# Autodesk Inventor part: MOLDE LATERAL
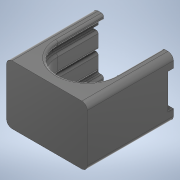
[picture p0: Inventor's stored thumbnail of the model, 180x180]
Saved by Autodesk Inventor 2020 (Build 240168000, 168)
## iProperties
Created: 2022-09
Part Number: MOLDE LATERAL
Material: PVC, no plastificado
Document SubType Name: Modeling
Designer: SEBAS
Density: 1.29 g/cm^3
Appearance: Suave - Negro
Author: SEBAS
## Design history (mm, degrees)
sketch "Boceto3"
  geometry: L1 (37, 54)-(37, 0); L2 (37, 0)-(27, 0); L3 (27, 0)-(27, 5); L4 (27, 5)-(32, 5); L5 (32, 5)-(32, 11); L6 (32, 11)-(27, 11); L7 (27, 11)-(27, 26); L8 (27, 26)-(32, 26); L9 (32, 26)-(32, 28); L10 (32, 28)-(27, 28); L11 (27, 28)-(27, 43); L12 (27, 43)-(32, 43); L13 (32, 43)-(32, 49); L14 (32, 49)-(27, 49); L15 (27, 49)-(27, 54); L16 (27, 54)-(37, 54); L17 (0, 0)-(0, 55); L18 (27, 5)-(27, 11); L19 (27, 26)-(27, 28); L20 (27, 49)-(27, 43); L21 (32, 49)-(32, 54); L22 (32, 5)-(32, 0)
  constraints: 44 end point, 10 perpendicular, 8 point on line, 5 collinear, 3 vertical, 2 horizontal alignment, 2 midpoint, 1 horizontal, 1 vertical alignment
  dimensions: "d27" = 32 distance from line of L17.start L5; "d28" = 10 distance of L1.end L2.end; "d29" = 5 distance of L4.end L3.end; "d30" = 5 distance of L14.end L15.end; "d33" = 2 distance of L8.end L9.end; "d34" = 15 distance of L10.end L11.end; "d35" = 6 distance of L4.end L5.end
sketch "Boceto4"
  geometry: L1 (0, -13.5)-(0, 13.5); L2 (37, 37)-(-37, 37); L3 (-37, 37)-(-37, -37); L4 (-37, -37)-(37, -37); L5 (37, -37)-(37, 37); L6 (37, 37)-(-37, -37); L7 (-37, 37)-(37, -37); L8 (-27, 27)-(27, 27); L9 (27, 27)-(27, -27); L10 (27, -27)-(-27, -27); L11 (-27, -27)-(-27, 27); L12 (-27, 27)-(27, -27); L13 (27, 27)-(-27, -27); L14 (37, 0)-(-37, 0); 4 further points
  constraints: 28 end point, 7 midpoint, 4 parallel, 4 perpendicular, 2 horizontal, 1 coincident
  dimensions: "d38" = 37 horizontal distance of L2.end point (0, 0); "d39" = 10 distance between parallel lines of L2 L8
revolve "Revolución2" stored, may be unused: angle "d40" = 180 deg
extrude "Extrusión2" join sketch "Boceto4" stored distance "d41" = 10; taper "d42" = 0 deg
revolve "Revolución3" stored, may be unused: angle "d43" = 90 deg
fillet "Empalme2" dims "d44" = 5
sketch "Boceto5"
  geometry: L1 (5, 5)-(0, 5) reference; L2 (0, 5)-(0, 0) reference; L3 (0, 0)-(5, 0) reference; L4 (5, 0)-(5, -6) reference; L5 (5, -6)-(0, -6) reference; L6 (0, -6)-(0, -21) reference; L7 (0, -21)-(5, -21) reference; L8 (5, -21)-(5, -23) reference; L9 (5, -23)-(0, -23) reference; L10 (0, -23)-(0, -38) reference; L11 (0, -38)-(5, -38) reference; L12 (5, -38)-(5, -44) reference; L13 (5, -44)-(0, -44) reference; L14 (0, -44)-(0, -49) reference; L15 (0, -49)-(5, -49) reference; L16 (10, -44)-(10, 0) reference; L17 (-64, -44)-(-64, 0) reference; L18 (-54, -49)-(-59, -49) reference; L19 (-54, -44)-(-54, -49) reference; L20 (-54, -44)-(-59, -44) reference; L21 (-59, -44)-(-59, -38) reference; L22 (-59, -38)-(-54, -38) reference; L23 (-54, -23)-(-54, -38) reference; L24 (-54, -23)-(-59, -23) reference; L25 (-59, -23)-(-59, -21) reference; L26 (-59, -21)-(-54, -21) reference; L27 (-54, -6)-(-54, -21) reference; L28 (-54, -6)-(-59, -6) reference; L29 (-59, -6)-(-59, 0) reference; L30 (-59, 0)-(-54, 0) reference; L31 (-54, 5)-(-54, 0) reference; L32 (-59, 5)-(-54, 5) reference; L33 (0, -23)-(0, -38) reference; L34 (0, -30.5)-(10, -30.5); L35 (0, -6)-(0, -21) reference; L36 (0, -13.5)-(10, -13.5); L37 (-54, -30.5)-(-64, -30.5); L38 (-54, -6)-(-54, -21) reference; L39 (-54, -13.5)-(-64, -13.5); L40 (-64, -44)-(-64, 0) reference; L41 (7.5, -28)-(2.5, -28); L42 (2.5, -28)-(2.5, -33); L43 (2.5, -33)-(7.5, -33); L44 (7.5, -33)-(7.5, -28); L45 (7.5, -28)-(2.5, -33); L46 (2.5, -28)-(7.5, -33); L47 (-56, -27.5)-(-62, -27.5); L48 (-62, -27.5)-(-62, -33.5); L49 (-62, -33.5)-(-56, -33.5); L50 (-56, -33.5)-(-56, -27.5); L51 (-56, -27.5)-(-62, -33.5); L52 (-62, -27.5)-(-56, -33.5); L53 (-56.5, -11)-(-61.5, -11); L54 (-61.5, -11)-(-61.5, -16); L55 (-61.5, -16)-(-56.5, -16); L56 (-56.5, -16)-(-56.5, -11); L57 (-56.5, -11)-(-61.5, -16); L58 (-61.5, -11)-(-56.5, -16); L59 (8, -10.5)-(2, -10.5); L60 (2, -10.5)-(2, -16.5); L61 (2, -16.5)-(8, -16.5); L62 (8, -16.5)-(8, -10.5); L63 (8, -10.5)-(2, -16.5); L64 (2, -10.5)-(8, -16.5)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; A1 r 5 centre (5, 0) between (10, 0) and (5, 5) reference; A2 r 5 centre (5, -44) between (5, -49) and (10, -44) reference; A3 r 5 centre (-59, 0) between (-59, 5) and (-64, 0) reference; A4 r 5 centre (-59, -44) between (-64, -44) and (-59, -49) reference; 9 further points; 1 other entity
  constraints: 60 end point, 15 midpoint, 9 parallel, 7 point on line, 6 equal length, 6 perpendicular, 4 horizontal, 1 vertical, 2 other
  dimensions: "d45" = 5 distance of L42.end L43.end; "d51" = 6 distance of L48.end L49.end
  node "Contorno proyectado1"
  node "Contorno proyectado2"
sketch "Boceto6"
  geometry: L1 (32, 28)-(-32, 28) reference; L2 (32, 26)-(32, 28) reference; L3 (32, 26)-(-32, 26) reference; L4 (-32, 28)-(-32, 26) reference; L5 (32, 27)-(-32, 27); L6 (-32, 28)-(-32, 26) reference; L7 (12.5, 14.5)-(-12.5, 14.5); L8 (-12.5, 14.5)-(-12.5, 39.5); L9 (-12.5, 39.5)-(12.5, 39.5); L10 (12.5, 39.5)-(12.5, 14.5); L11 (12.5, 14.5)-(-12.5, 39.5); L12 (-12.5, 14.5)-(12.5, 39.5); 2 further points
  constraints: 14 end point, 5 midpoint, 2 parallel, 2 perpendicular, 1 horizontal
  dimensions: "d53" = 25 distance of L8.end L9.end
extrude "Extrusión5" cut sketch "Boceto6" distance "d54" = 33; taper "d55" = 0 deg
fillet "Empalme5" dims "d56" = 2
fillet "Empalme7" dims "d60" = 1
fillet "Empalme8" dims "d61" = 1
extrude "Extrusión7" join sketch "Boceto5" distance "d65" = 42; taper "d66" = 0 deg
sketch "Boceto8"
  geometry: L1 (0, -6)-(0, -21) reference; L2 (0, -21)-(5, -21) reference; L3 (5, -21)-(5, -23) reference; L4 (5, -23)-(0, -23) reference; L5 (0, -23)-(0, -38) reference; L6 (0, -38)-(5, -38) reference; L7 (5, -38)-(5, -44) reference; L8 (5, -44)-(0, -44) reference; L9 (0, -44)-(0, -49) reference; L10 (0, -49)-(5, -49) reference; L11 (10, -44)-(10, 0) reference; L12 (5, 5)-(0, 5) reference; L13 (0, 5)-(0, 0) reference; L14 (0, 0)-(5, 0) reference; L15 (5, 0)-(5, -6) reference; L16 (5, -6)-(0, -6) reference; L17 (-59, 0)-(-54, 0) reference; L18 (-54, 0)-(-54, 5) reference; L19 (-54, 5)-(-59, 5) reference; L20 (-64, 0)-(-64, -44) reference; L21 (-59, -49)-(-54, -49) reference; L22 (-54, -49)-(-54, -44) reference; L23 (-54, -44)-(-59, -44) reference; L24 (-59, -44)-(-59, -38) reference; L25 (-59, -38)-(-54, -38) reference; L26 (-54, -38)-(-54, -23) reference; L27 (-54, -23)-(-59, -23) reference; L28 (-59, -23)-(-59, -21) reference; L29 (-59, -21)-(-54, -21) reference; L30 (-54, -21)-(-54, -6) reference; L31 (-54, -6)-(-59, -6) reference; L32 (-59, -6)-(-59, 0) reference; L33 (-54, -44)-(-54, 0); L34 (-54, 0)-(-59, 0); L35 (-59, 0)-(-59, -6); L36 (-59, -6)-(-64, -6); L37 (-64, -6)-(-64, -38); L38 (-64, 0)-(-64, -44) reference; L39 (-64, -38)-(-59, -38); L40 (-59, -38)-(-59, -44); L41 (-54, -44)-(-59, -44) reference; L42 (-59, -44)-(-54, -44); L43 (5, -44)-(5, -38); L44 (5, -38)-(10, -38); L45 (10, -38)-(10, -6); L46 (10, -44)-(10, 0) reference; L47 (10, -6)-(5, -6); L48 (0, 0)-(5, 0) reference; L49 (5, -6)-(5, 0); L50 (5, 0)-(0, 0); L51 (0, 0)-(0, -44); L52 (0, -44)-(5, -44); A1 r 5 centre (5, -44) between (5, -49) and (10, -44) reference; A2 r 5 centre (5, 0) between (10, 0) and (5, 5) reference; A3 r 5 centre (-59, 0) between (-59, 5) and (-64, 0) reference; A4 r 5 centre (-59, -44) between (-64, -44) and (-59, -49) reference; 11 further points
  constraints: 32 end point, 7 perpendicular, 4 point on line, 4 vertical, 3 horizontal
  node "Contorno proyectado4"
  node "Contorno proyectado5"
extrude "Extrusión8" cut sketch "Boceto8" distance "d67" = 5; taper "d68" = 0 deg
fillet "Empalme9" dims "d69" = 2
sketch "Boceto10"
  geometry: L1 (0, -19)-(0, -8) reference; L2 (5, -21)-(2, -21) reference; L3 (5, -23)-(5, -21) reference; L4 (2, -23)-(5, -23) reference; L5 (0, -36)-(0, -25) reference; L6 (5, -38)-(2, -38) reference; L7 (10, -38)-(5, -38) reference; L8 (10, -6)-(10, -38) reference; L9 (5, -6)-(10, -6) reference; L10 (2, -6)-(5, -6) reference; L11 (-54, -8)-(-54, -19) reference; L12 (-59, -6)-(-56, -6) reference; L13 (-64, -6)-(-59, -6) reference; L14 (-64, -38)-(-64, -6) reference; L15 (-59, -38)-(-64, -38) reference; L16 (-56, -38)-(-59, -38) reference; L17 (-54, -25)-(-54, -36) reference; L18 (-59, -23)-(-56, -23) reference; L19 (-59, -21)-(-59, -23) reference; L20 (-56, -21)-(-59, -21) reference; L21 (-54, -30.5)-(-64, -30.5); L22 (-54, -13.5)-(-64, -13.5); L23 (-64, -38)-(-64, -6) reference; L24 (-54, -8)-(-54, -19) reference; L25 (-54, -25)-(-54, -36) reference; L26 (0, -36)-(0, -25) reference; L27 (0, -30.5)-(10, -30.5); L28 (10, -6)-(10, -38) reference; L29 (0, -13.5)-(10, -13.5); C1 r 1.5 at (5, -30.5); C2 r 1.5 at (5, -13.5); C3 r 1.5 at (-59, -13.5); C4 r 1.5 at (-59, -30.5); A1 r 2 centre (2, -8) between (2, -6) and (0, -8) reference; A2 r 2 centre (2, -19) between (0, -19) and (2, -21) reference; A3 r 2 centre (2, -25) between (2, -23) and (0, -25) reference; A4 r 2 centre (2, -36) between (0, -36) and (2, -38) reference; A5 r 2 centre (-56, -19) between (-56, -21) and (-54, -19) reference; A6 r 2 centre (-56, -8) between (-54, -8) and (-56, -6) reference; A7 r 2 centre (-56, -36) between (-56, -38) and (-54, -36) reference; A8 r 2 centre (-56, -25) between (-54, -25) and (-56, -23) reference; 1 further point
  constraints: 8 end point, 8 midpoint, 4 centre point, 4 perpendicular, 4 point on line, 3 equal radius, 1 horizontal
  dimensions: "d70" = 3 diameter of C1
extrude "Extrusión9" cut sketch "Boceto10" distance "d71" = 30; taper "d72" = 0 deg
fillet "Empalme10" dims "d73" = 1
sketch "Boceto11"
  geometry: L1 (5, -10)-(5, -11.702) reference; L2 (6.702, -10)-(5, -10) reference; L3 (59, -11.702)-(59, -10) reference; L4 (59, -10)-(57.298, -10) reference; A1 r 37 centre (32, -37) between (6.702, -10) and (5, -11.702) reference; A2 r 37 centre (32, -37) between (59, -11.702) and (57.298, -10) reference; 1 further point
extrude "Extrusión10" join sketch "Boceto11" stored distance "d74" = 30; taper "d75" = 0 deg
node "Sólido2"
node "Contorno proyectado3"
node "Contorno proyectado6"
node "Contorno proyectado7"
